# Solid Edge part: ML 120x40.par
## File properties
Title: ML 120x40
Author: DESYS
Template: Iso Part.par
Last saved by: Administrator
Revision: 20
Application: Solid Edge
Tipo di contenuto documento: 0
Accuracy: 0,990
Document Number: 3003
Revision: 0
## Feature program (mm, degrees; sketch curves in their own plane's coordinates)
sketch for "unnamed Protrusion 1" plane through (10.8674, 0, 10.8674) normal (0, -1, 0) x-axis (1, 0, 0)
  line (-360.8674, -210.8674) -> (246.6326, -210.8674)
  line (246.6326, -210.8674) -> (246.6326, 189.1326)
  line (246.6326, 189.1326) -> (-360.8674, 189.1326)
  line (-360.8674, 189.1326) -> (-360.8674, -210.8674)
  dimension (linear) = 246.6326
extrude "unnamed Protrusion 1" add finite 50 along -normal
sketch for "ProtrusioneEstrusa_2" plane through (0, 50, 0) normal (0, 1, 0) x-axis (1, 0, 0)
  line (-175, -200) -> (175, -200)
  line (175, -200) -> (175, 100)
  line (175, 100) -> (-175, 100)
  line (-175, 100) -> (-175, -200)
  dimension (linear) = 175
  dimension (linear) = 175
extrude "ProtrusioneEstrusa_2" add finite 90 along +normal
sketch for "ProtrusioneEstrusa_3" plane through (0, 50, 0) normal (0, 1, 0) x-axis (1, 0, 0)
  line (0, 0) -> (0, 0)
  line (-307.5, -175) -> (257.5, -175)
  line (257.5, 145) -> (257.5, -175)
  line (257.5, 145) -> (-307.5, 145)
  line (-307.5, 145) -> (-307.5, -175)
  dimension (linear) = 307.5
  dimension (linear) = 257.5
extrude "ProtrusioneEstrusa_3" add finite 60 along +normal
sketch for "ScavoEstrusione_3" plane through (0, 0, 0) normal (0, -1, 0) x-axis (0, 0, 1)
  line (-185, -335) -> (185, -335)
  line (185, -335) -> (185, 335)
  line (185, 335) -> (-185, 335)
  line (-185, 335) -> (-185, -335)
extrude "ScavoEstrusione_3" cut finite 10 along -normal
sketch for "ScavoEstrusione_1" plane through (0, 80, -145) normal (0, 0, -1) x-axis (1, 0, 0)
  arc centre (-191.9024, 108.9759) radius 140 from (-307.5, 30) to (-175, -30) ccw
  line (-175, -30) -> (-175, -63.2381)
  line (-175, -63.2381) -> (-319.7189, -63.2381)
  line (-319.7189, 30) -> (-319.7189, -63.2381)
  line (-307.5, 30) -> (-319.7189, 30)
extrude "ScavoEstrusione_1" cut finite 1320 along -normal
sketch for "unnamed Cutout 1" plane through (257.5, 25, 0) normal (1, 0, 0) x-axis (0, 0, 1)
  arc centre (-57.0477, -5.9108) radius 90 from (-145, -25) to (-100, -85) ccw
  line (-100, -85) -> (-100, -142.9417)
  line (-100, -142.9417) -> (-237.3462, -142.9417)
  line (-237.3462, -142.9417) -> (-237.3462, -25)
  line (-145, -25) -> (-237.3462, -25)
extrude "unnamed Cutout 1" cut through along -normal
sketch for "ScavoEstrusione_4" plane through (0, 70, 65) normal (0, 0, 1) x-axis (-1, 0, 0)
  line (-70, -40) -> (70, -40)
  arc centre (58.1881, 99.5008) radius 140 from (70, -40) to (192.5, 60) ccw
  line (192.5, 60) -> (192.5, 106.8583)
  line (-207.5, 106.8583) -> (192.5, 106.8583)
  line (-207.5, 60) -> (-207.5, 106.8583)
  arc centre (-73.3242, 99.9605) radius 140 from (-207.5, 60) to (-70, -40) ccw
  dimension (linear) = 70
  dimension (linear) = 207.5
extrude "ScavoEstrusione_4" cut finite 150 along -normal  Profile_Plane1_Distance = 135 mm
draft "Spoglia_2"  Angles1 = 42 deg
draft "Spoglia_3"  Angles1 = 5 deg
sketch for "ScavoEstrusione_5" plane through (0, 18.0435, 18.0435) normal (1, 0, 0) x-axis (0, 1, 0)
  line (144.3482, -93.0435) -> (101.9565, -93.0435)
  line (101.9565, -93.0435) -> (101.9565, 92.5984)
  line (101.9565, 92.5984) -> (6.9565, 92.5984)
  line (6.9565, 92.5984) -> (6.9565, 161.9565)
  line (6.9565, 161.9565) -> (148.2952, 161.9565)
extrude "ScavoEstrusione_5" cut finite 300 symmetric
sketch for "unnamed Cutout 2" plane through (0, 70, 200) normal (0, 0, 1) x-axis (-1, 0, 0)
  line (95, -5) -> (85, -5)
  arc centre (85, 5) radius 10 from (85, 15) to (85, -5) ccw
  line (85, 15) -> (95, 15)
  arc centre (95, 5) radius 10 from (95, -5) to (95, 15) ccw
  dimension (linear) = 95
  dimension (linear) = 85
extrude "unnamed Cutout 2" cut through along -normal
fillet "Rotondo_1" radius 30
sketch for "Foro_1" plane through (0, 10, 120) normal (0, -1, 0) x-axis (0, 0, 1)
  hole centre (10, 0) bore radius 17.5
hole "Foro_1" diameter 35 through
sketch for "ProtrusioneEstrusa_4" plane through (0, 120, -18.4901) normal (0, 1, 0) x-axis (0, 0, 1)
  circle centre (23.4901, 0) radius 35
  dimension (linear) = 23.4901
extrude "ProtrusioneEstrusa_4" add finite 45 along +normal
sketch for "Foro_2" plane through (0, 165, 0) normal (0, 1, 0) x-axis (-1, 0, 0)
  hole centre (0, 5) bore radius 25
hole "Foro_2" diameter 50 through
sketch for "ProtrusioneEstrusa_5" plane through (0, 18.407, 18.407) normal (1, 0, 0) x-axis (0, 1, 0)
  line (135.6089, 45.1462) -> (135.6089, 16.0718)
  line (135.6089, 16.0718) -> (95.0929, 16.0718)
  line (95.0929, 16.0718) -> (95.0929, 76.6273)
  line (95.0929, 76.6273) -> (-4.939, 87.3812)
  line (-4.939, 87.3812) -> (-4.939, 108.3029)
  line (-4.939, 108.3029) -> (77.9252, 105.1014)
  arc centre (75.6089, 45.1462) radius 60 from (77.9252, 105.1014) to (135.6089, 45.1462) cw
extrude "ProtrusioneEstrusa_5" add finite 30 symmetric
sketch for "Foro_3" plane through (25.0453, 25.0453, 0) normal (0, 0, -1) x-axis (-1, 0, 0)
  hole centre (25.0453, -0.0453) bore radius 10
hole "Foro_3" diameter 20 to key point
fillet "Rotondo_7" radius 5
fillet "Rotondo_9" radius 30
fillet "Rotondo_14" radius 10
fillet "Rotondo_15" radius 10
fillet "Rotondo_16" radius 5
fillet "Rotondo_17" radius 10
fillet "Rotondo_18" radius 5
sketch for "unnamed Cutout 3" plane through (0, 0, 0) normal (0, -1, 0) x-axis (1, 0, 0)
extrude "unnamed Cutout 3" cut through
fillet "Rotondo_45" radius 10
fillet "Rotondo_46" radius 5
mirror "unnamed Mirror 1" of "unnamed Protrusion 1", "ProtrusioneEstrusa_2", "ProtrusioneEstrusa_3", "ScavoEstrusione_3", "ScavoEstrusione_1", "unnamed Cutout 1", "ScavoEstrusione_4", "Spoglia_2", "Spoglia_3", "ScavoEstrusione_5", "unnamed Cutout 2", "Rotondo_1" about plane through (257.5, 55, 0) normal (1, 0, 0)
extrude "unnamed Protrusion 2" add finite 50
extrude "unnamed Protrusion 3" add finite 90
extrude "unnamed Protrusion 4" add finite 60
extrude "unnamed Cutout 4" cut finite 10
extrude "unnamed Cutout 5" cut finite 1320
extrude "unnamed Cutout 6" cut through
extrude "unnamed Cutout 7" cut finite 150
draft "unnamed Draft 1"
draft "unnamed Draft 2"
extrude "unnamed Cutout 8" cut finite 300 symmetric
extrude "unnamed Cutout 9" cut through
fillet "unnamed Round 1"
hole "unnamed Hole 1" through
extrude "unnamed Protrusion 5" add finite 45
hole "unnamed Hole 2" through
extrude "unnamed Protrusion 6" add finite 30 symmetric
hole "unnamed Hole 3" finite
fillet "unnamed Round 2"
fillet "unnamed Round 3"
fillet "unnamed Round 4"
fillet "unnamed Round 5"
fillet "unnamed Round 6"
fillet "unnamed Round 7"
fillet "unnamed Round 8"
fillet "unnamed Round 9"
fillet "unnamed Round 10"
sketch for "unnamed Protrusion 7" #1 plane through (0, 140, 45) normal (0, 1, 0) x-axis (0, 0, 1)
sketch for "unnamed Protrusion 7" #2 plane through (0, 140, 45) normal (0, 1, 0) x-axis (0, 0, 1)
  line (125, 350.1539) -> (125, 175)
  line (125, 175) -> (155, 175)
  line (155, 175) -> (155, 350.1539)
  line (155, 350.1539) -> (125, 350.1539)
extrude "unnamed Protrusion 7" add through along -normal
sketch for "unnamed Cutout 10" plane through (250, 140, 45) normal (0, 1, 0) x-axis (-1, 0, 0)
  line (-115, 125) -> (-115, -120)
  line (-115, -120) -> (100, -120)
  line (100, -120) -> (100, 125)
  line (100, 125) -> (-115, 125)
extrude "unnamed Cutout 10" cut along +normal
sketch for "unnamed Cutout 11" plane through (250, 70, 200) normal (0, 0, 1) x-axis (-1, 0, 0)
  line (-325, -100) -> (310, -100)
  line (310, -100) -> (310, 460)
  line (310, 460) -> (810, -40)
  line (810, -40) -> (220, -40)
  line (-325, -585) -> (220, -40)
  line (-325, -585) -> (-325, -100)
  dimension (linear) = 810
extrude "unnamed Cutout 11" cut through along -normal
sketch for "ScavoEstrusione_35" plane through (250, 70, 195) normal (0, 0, 1) x-axis (-1, 0, 0)
  line (-50, -90) -> (50, -90)
  line (50, -90) -> (50, -40)
  line (50, -40) -> (30, 10)
  line (30, 10) -> (-30, 10)
  line (-50, -40) -> (-30, 10)
  line (-50, -40) -> (-50, -90)
  dimension (linear) = 30
  dimension (linear) = 30
extrude "ScavoEstrusione_35" cut finite 40 along -normal
fillet "Rotondo_57" radius 5
fillet "Rotondo_58" radius 5
fillet "Rotondo_59" radius 5
fillet "Rotondo_60" radius 10
fillet "Rotondo_61" radius 10
fillet "Rotondo_62" radius 5
fillet "Rotondo_63" radius 5
fillet "Rotondo_64" radius 10
sketch for "unnamed Cutout 12" plane through (-194.9517, 110, 31.5418) normal (0, 1, 0) x-axis (0, 0, 1)
extrude "unnamed Cutout 12" cut to key point along -normal
fillet "Rotondo_65" radius 20
fillet "Rotondo_66" radius 10
fillet "Rotondo_67" radius 40
fillet "Rotondo_68" radius 5
extrude "unnamed Cutout 13" cut finite 60
fillet "unnamed Round 11"
fillet "unnamed Round 12"
fillet "unnamed Round 13"
fillet "unnamed Round 14"
sketch for "Foro_13" plane through (250, 10, 0.4126) normal (0, -1, 0) x-axis (1, 0, 0)
hole "Foro_13" diameter 35 through
sketch for "unnamed Hole 4" plane through (250, 10, 0.4126) normal (0, -1, 0) x-axis (1, 0, 0)
  hole centre (265, 144.5874) bore radius 17.5
hole "unnamed Hole 4" through
fillet "Rotondo_73" radius 5
mirror "unnamed Mirror 2" of "unnamed Cutout 12", "Rotondo_65", "Rotondo_66", "Rotondo_67", "Rotondo_68" about plane through (257.5, 25, 0) normal (-1, 0, 0)
pattern "unnamed Pattern 1" of "Foro_13", "unnamed Hole 4"
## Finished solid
Body 1: solid body, 306 faces, 735 edges, 430 vertices.
  Faces by surface: cylinder 141, plane 73, blend 48, torus 44
  Edges by curve: line 319, circle 218, intersection 112, ellipse 86
Bounding box of the edges (mm; curved faces can reach further): 1215.000 x 165.000 x 400.000, from (-350, 0, -200) to (865, 165, 200).
Cylindrical faces by radius (mm): R5 x72, R10 x46, R17.5 x2, R20 x2, R25 x2, R30 x4, R35 x2, R40 x2, R60 x2, R90 x1, R140 x6
Toroidal faces (ring radius, tube radius in mm): R5 r5 x4, R15 r5 x8, R15 r10 x2, R22.5 r5 x2, R25 r5 x2, R30 r5 x2, R35 r5 x8, R35 r10 x2, R44.4524 r10 x2, R45 r10 x2, R55 r5 x4, R130 r10 x6
Planar faces by outward normal: +x 9, +y 18, +z 12, -x 9, -y 6, -z 11, oblique 8
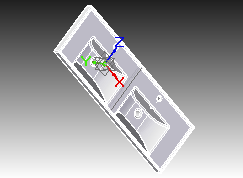
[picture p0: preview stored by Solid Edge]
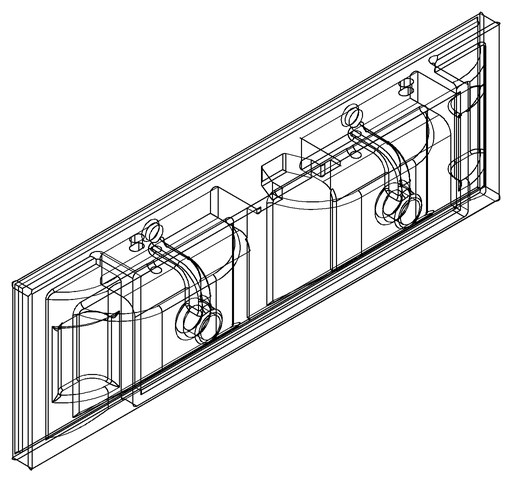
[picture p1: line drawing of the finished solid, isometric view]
